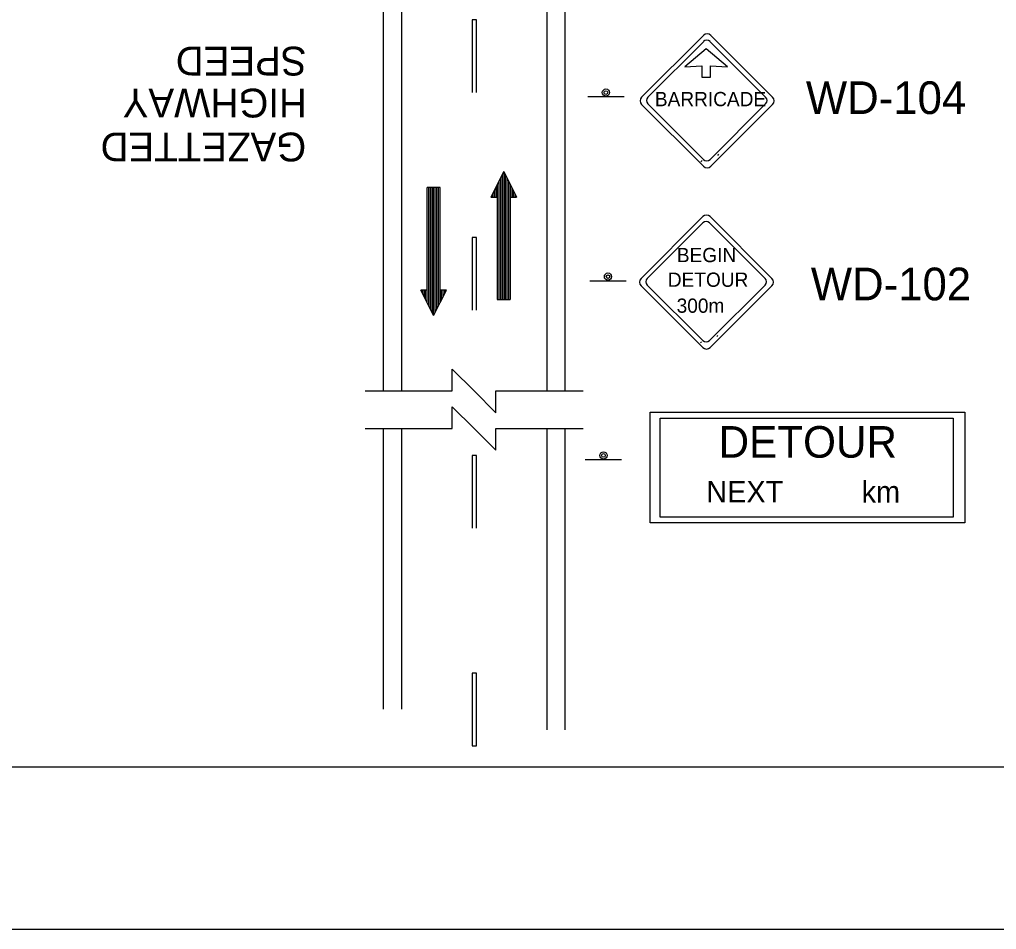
# Model space of a CAD drawing. Extents: x 1806 to 2022, y 110 to 389.
# Drawn here: x 1853.5 to 1918.6, y 110.2 to 170.8 of the extents above; entities that cross this region are included whole.
import ezdxf

# ---------------------------------------------------------------- set-up
doc = ezdxf.new("R2010")
doc.units = 0
for name, color, linetype in [('Level 10', 7, 'Continuous'), ('Level 2', 7, 'Continuous'), ('Level 20', 7, 'Continuous'), ('Level 44', 7, 'Continuous'), ('Level 50', 7, 'Continuous'), ('Level 60', 7, 'Continuous')]:
    doc.layers.add(name, color=color, linetype=linetype)

msp = doc.modelspace()

# ---------------------------------------------------------------- linework, layer by layer
at = {"layer": 'Level 10'}
for p, q in [((1877.715, 208.881), (1877.715, 146.057)), ((1878.925, 208.881), (1878.925, 146.057)), ((1888.603, 208.881), (1888.603, 146.057)), ((1889.812, 208.881), (1889.812, 146.057)), ((1877.715, 143.557), (1877.715, 124.854)), ((1878.925, 143.557), (1878.925, 124.854)), ((1888.603, 143.557), (1888.603, 123.478)), ((1889.812, 143.557), (1889.812, 123.478))]:
    msp.add_line(p, q, dxfattribs=at)
for points in [[(1895.502, 144.637), (1916.449, 144.637), (1916.449, 137.266), (1895.502, 137.266)], [(1896.148, 144.249), (1915.674, 144.249), (1915.674, 137.654), (1896.148, 137.654)]]:
    msp.add_lwpolyline(points, close=True, dxfattribs=at)
at = {"layer": 'Level 2'}
for p, q in [((1883.628, 170.786), (1883.628, 165.948)), ((1883.918, 170.786), (1883.628, 170.786)), ((1883.918, 165.948), (1883.918, 170.786)), ((1898.956, 161.401), (1898.878, 161.323)), ((1900.05, 161.826), (1899.972, 161.748)), ((1883.628, 156.272), (1883.628, 151.434)), ((1883.918, 156.272), (1883.628, 156.272)), ((1883.918, 151.434), (1883.918, 156.272)), ((1900.011, 149.755), (1899.933, 149.677)), ((1898.918, 149.33), (1898.84, 149.252)), ((1883.628, 141.758), (1883.628, 136.92)), ((1883.918, 141.758), (1883.628, 141.758)), ((1883.918, 136.92), (1883.918, 141.758)), ((1883.628, 127.244), (1883.628, 122.406)), ((1883.918, 127.244), (1883.628, 127.244)), ((1883.918, 122.406), (1883.918, 127.244)), ((1883.628, 122.406), (1883.918, 122.406))]:
    msp.add_line(p, q, dxfattribs=at)
at = {"layer": 'Level 20'}
for points in [[(1876.505, 146.057), (1882.311, 146.057), (1882.311, 147.508), (1883.762, 146.057), (1885.214, 144.605), (1885.214, 146.057), (1891.019, 146.057)], [(1876.505, 143.557), (1882.311, 143.557), (1882.311, 145.008), (1883.762, 143.557), (1885.214, 142.105), (1885.214, 143.557), (1891.019, 143.557)]]:
    msp.add_lwpolyline(points, dxfattribs=at)
at = {"layer": 'Level 44'}
for p, q in [((1899.043, 169.74), (1894.923, 165.627)), ((1895.336, 165.623), (1899.043, 169.325)), ((1899.481, 169.325), (1903.185, 165.623)), ((1903.644, 165.627), (1899.53, 169.74)), ((1899.225, 168.84), (1897.809, 167.647)), ((1900.64, 167.647), (1899.225, 168.84)), ((1897.809, 167.647), (1898.94, 167.708)), ((1898.94, 167.708), (1898.94, 166.952)), ((1899.508, 166.952), (1899.508, 167.708)), ((1899.508, 167.708), (1900.64, 167.647)), ((1898.94, 166.952), (1899.504, 166.952)), ((1891.333, 165.663), (1893.752, 165.663)), ((1894.923, 165.138), (1899.043, 161.02)), ((1894.926, 165.138), (1894.923, 165.138)), ((1899.043, 161.477), (1895.336, 165.183)), ((1903.185, 165.183), (1899.481, 161.477)), ((1899.53, 161.02), (1903.644, 165.138)), ((1899.005, 157.669), (1894.884, 153.555)), ((1903.605, 153.555), (1899.492, 157.669)), ((1895.298, 153.551), (1899.005, 157.254)), ((1899.443, 157.254), (1903.146, 153.551)), ((1891.469, 153.402), (1893.888, 153.402)), ((1894.884, 153.067), (1899.005, 148.948)), ((1894.888, 153.067), (1894.884, 153.067)), ((1899.005, 149.406), (1895.298, 153.112)), ((1903.146, 153.112), (1899.443, 149.406)), ((1899.492, 148.948), (1903.605, 153.067)), ((1891.165, 141.488), (1893.586, 141.488))]:
    msp.add_line(p, q, dxfattribs=at)
for centre, radius in [((1892.547, 165.933), 0.242), ((1892.547, 165.933), 0.121), ((1892.683, 153.672), 0.242), ((1892.683, 153.672), 0.121), ((1892.38, 141.76), 0.242), ((1892.38, 141.76), 0.121)]:
    msp.add_circle(centre, radius, dxfattribs=at)
for centre, radius, start, end in [((1899.286, 169.498), 0.345, 45, 135), ((1899.261, 169.107), 0.31, 45, 135), ((1895.169, 165.382), 0.345, 135, 224.99999), ((1895.557, 165.403), 0.31, 135, 224.99999), ((1902.966, 165.403), 0.31, 315, 45), ((1903.402, 165.382), 0.345, 315, 45), ((1899.261, 161.698), 0.31, 225, 315), ((1899.286, 161.266), 0.345, 225, 315), ((1899.247, 157.427), 0.345, 45, 135), ((1899.223, 157.036), 0.31, 45, 135), ((1895.131, 153.31), 0.345, 135, 224.99999), ((1895.518, 153.331), 0.31, 135, 224.99999), ((1902.928, 153.331), 0.31, 315, 45), ((1903.364, 153.31), 0.345, 315, 45), ((1899.223, 149.627), 0.31, 225, 315), ((1899.247, 149.194), 0.345, 225, 315)]:
    msp.add_arc(centre, radius, start, end, dxfattribs=at)
at = {"layer": 'Level 50'}
for p, q in [((1885.737, 160.674), (1884.884, 158.967)), ((1885.524, 160.247), (1885.524, 152.14)), ((1885.631, 160.46), (1885.631, 152.14)), ((1885.737, 160.674), (1885.737, 152.14)), ((1885.737, 160.674), (1886.591, 158.967)), ((1885.844, 160.46), (1885.844, 152.14)), ((1885.951, 160.247), (1885.951, 152.14)), ((1880.643, 152.778), (1880.643, 159.605)), ((1881.496, 159.605), (1880.643, 159.605)), ((1880.643, 151.925), (1880.643, 159.605)), ((1880.749, 151.712), (1880.749, 159.605)), ((1880.856, 151.498), (1880.856, 159.605)), ((1880.963, 151.285), (1880.963, 159.605)), ((1881.069, 151.072), (1881.069, 159.605)), ((1881.176, 151.285), (1881.176, 159.605)), ((1881.283, 151.498), (1881.283, 159.605)), ((1881.389, 151.712), (1881.389, 159.605)), ((1881.496, 152.778), (1881.496, 159.605)), ((1881.496, 151.925), (1881.496, 159.605)), ((1885.204, 159.607), (1885.204, 158.967)), ((1885.311, 159.82), (1885.311, 152.14)), ((1885.417, 160.034), (1885.417, 152.14)), ((1886.057, 160.034), (1886.057, 152.14)), ((1886.164, 159.82), (1886.164, 152.14)), ((1886.271, 159.607), (1886.271, 158.967)), ((1884.884, 158.967), (1885.311, 158.967)), ((1884.991, 159.18), (1884.991, 158.967)), ((1885.097, 159.394), (1885.097, 158.967)), ((1885.311, 158.967), (1885.311, 152.14)), ((1886.164, 158.967), (1886.164, 152.14)), ((1886.164, 158.967), (1886.591, 158.967)), ((1886.377, 159.394), (1886.377, 158.967)), ((1886.484, 159.18), (1886.484, 158.967)), ((1881.069, 151.072), (1880.216, 152.778)), ((1880.643, 152.778), (1880.216, 152.778)), ((1880.323, 152.565), (1880.323, 152.778)), ((1880.429, 152.352), (1880.429, 152.778)), ((1880.536, 152.138), (1880.536, 152.778)), ((1881.069, 151.072), (1881.923, 152.778)), ((1881.923, 152.778), (1881.496, 152.778)), ((1881.603, 152.138), (1881.603, 152.778)), ((1881.709, 152.352), (1881.709, 152.778)), ((1881.816, 152.565), (1881.816, 152.778)), ((1885.311, 152.14), (1886.164, 152.14))]:
    msp.add_line(p, q, dxfattribs=at)
at = {"layer": 'Level 60'}
for points in [[(1805.588, 389.179), (2021.588, 389.179), (2021.588, 110.179), (1805.588, 110.179)], [(1824.714, 378.37), (2011.588, 378.37), (2011.588, 120.988), (1824.714, 120.988)]]:
    msp.add_lwpolyline(points, close=True, dxfattribs=at)

# ---------------------------------------------------------------- texts
at = {"layer": 'Level 10'}
for s, height, rotation, p in [('SPEED', 1.92, 180, (1872.599, 168.991)), ('WD-104', 2.1774, 360, (1905.866, 164.505)), ('HIGHWAY', 1.92, 180, (1872.625, 166.196)), ('GAZETTED', 1.92, 180, (1872.582, 163.27)), ('WD-102', 2.1774, 360, (1906.194, 152.094)), ('DETOUR', 2.1047, 360, (1900.05, 141.609)), ('NEXT', 1.4375, 360, (1899.232, 138.624)), ('km', 1.4375, 360, (1909.579, 138.615))]:
    msp.add_text(s, height=height, rotation=rotation, dxfattribs=at).set_placement(p)
at = {"layer": 'Level 44'}
msp.add_text('BARRICADE', height=0.95, rotation=360, dxfattribs=at).set_placement((1895.807, 165.025))
for s, p in [('BEGIN', (1897.27, 154.636)), ('DETOUR', (1896.669, 152.992)), ('300m', (1897.257, 151.262))]:
    msp.add_text(s, height=0.95, dxfattribs=at).set_placement(p)

doc.saveas('drawing.dxf')
